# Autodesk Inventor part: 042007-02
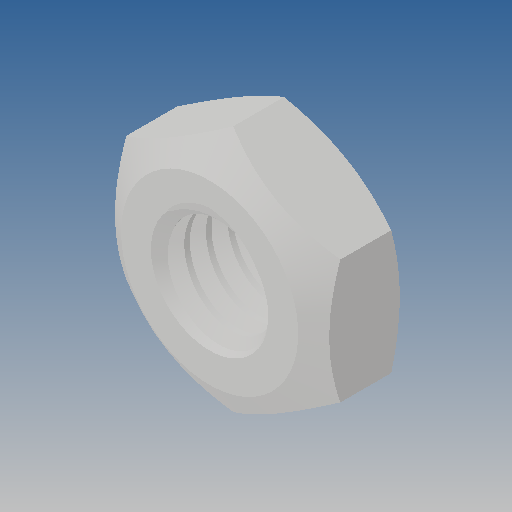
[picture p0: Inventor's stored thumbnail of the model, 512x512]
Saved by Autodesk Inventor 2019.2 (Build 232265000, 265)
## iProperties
Created: 2012-09
Part Number: 042007-02
Material: Ogólny
Document SubType Name: Modeling
Designer: CADENGINEERING4
Density: 1 g/cm^3
Appearance: Domyślna
Author: CADENGINEERING4
Revision Number: ÈÎºÎ
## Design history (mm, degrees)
feature "ÇÐ³ý-É¨Ãè1"
node "Bryła1"
